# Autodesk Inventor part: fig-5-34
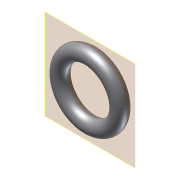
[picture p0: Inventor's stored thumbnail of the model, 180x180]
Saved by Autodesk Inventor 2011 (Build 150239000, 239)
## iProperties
Created: 2010-02
Part Number: fig-5-34
Document SubType Name: Modeling
Designer: CADSoft
Density: 1 g/cm^3
Author: CADSoft
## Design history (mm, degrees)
sketch "Sketch1"
  geometry: L1 (0, 21.37)-(0, -16.247); C1 r 5 at (20.026, 0); 1 further point
  constraints: 2 end point, 1 centre point
  dimensions: "d0" = 10 diameter of C1
revolve "Revolution1" sketch "Sketch1" stored, may be unused: angle "d1" = 90 deg
workplane "Work Plane1"
body "Solid1"
